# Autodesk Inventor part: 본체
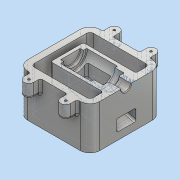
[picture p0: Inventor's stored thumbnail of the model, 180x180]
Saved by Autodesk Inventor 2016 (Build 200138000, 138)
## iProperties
Created: 2018-01
Part Number: 본체
Material: 알루미늄 6061
Document SubType Name: Modeling
Designer: Administrator
Density: 2.7 g/cm^3
Appearance: 알루미늄 - 평지
Mass: 995.304 g
Surface Area: 835.211 cm^2
Volume: 368.631 cm^3
Author: Administrator
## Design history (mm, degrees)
sketch "스케치4"
  geometry: L1 (-55, 55)-(55, 55); L2 (55, 55)-(55, -55); L3 (55, -55)-(-55, -55); L4 (-55, -55)-(-55, 55); L5 (-55, 55)-(55, -55); L6 (55, 55)-(-55, -55); L7 (45, 45)-(-45, 45); L8 (-45, 45)-(-45, -45); L9 (-45, -45)-(45, -45); L10 (45, -45)-(45, 45); 3 further points
  constraints: 20 end point, 2 midpoint, 2 parallel, 2 point on line, 1 horizontal, 1 perpendicular
  dimensions: "d17" = 110 distance of L1.end L2.end; "d18" = 110 distance of L1.start L1.end; "d19" = 90 distance of L9.end L7.start; "d20" = 10 distance between parallel lines of L2 L10; "d21" = 10 distance between parallel lines of L1 L7; "d22" = 10 distance between parallel lines of L4 L8; "d23" = 90 distance of L8.end L9.end
extrude "돌출2" new body sketch "스케치4" distance "d27" = 65; taper "d28" = 0 deg
sketch "스케치5"
  geometry: L1 (-45, -45)-(-45, 45) reference; L2 (-45, 45)-(45, 45) reference; L3 (45, 45)-(45, -45) reference; L4 (45, -45)-(-45, -45) reference; L5 (-55, 55)-(-55, -55) reference; L6 (-55, -55)-(55, -55) reference; L7 (55, -55)-(55, 55) reference; L8 (55, 55)-(-55, 55) reference; L9 (-55, 55)-(55, 55) reference; 1 further point
node "작업 평면1"
sketch "스케치6"
  geometry: L1 (-55, 55)-(55, 55) reference; L2 (-35.5, 65)-(-20.5, 65); L3 (-20.5, 65)-(-20.5, 55); L4 (-20.5, 55)-(-35.5, 55); L5 (-35.5, 55)-(-35.5, 65); L6 (-55, 55)-(-55, -55) reference; A1 r 7.5 centre (-28, 65) between (-20.5, 65) and (-35.5, 65); 1 further point
  constraints: 8 end point, 2 parallel, 2 point on circle, 1 centre point, 1 horizontal, 1 perpendicular, 1 point on line, 1 tangent
  dimensions: "d30" = 7.5 radius of A1; "d31" = 27 distance from line of L6 A1.centre; "d32" = 10 distance from line of A1.centre L1
extrude "돌출3" join sketch "스케치6" distance "d33" = 20; taper "d34" = 0 deg
sketch "스케치8"
  geometry: L1 (110, -65)-(110, 0) reference; L2 (0, 0)-(110, 0) reference; 2 further points
  constraints: 1 other
  dimensions: "d38" = 20 distance from line of L2 point (55, -20); "d39" = 55 distance from line of L1 point (55, -20)
feature "엠보싱1" sketch "스케치8" dims "d17" = 110, "d18" = 110, "d19" = 90, "d20" = 10, "d21" = 10, "d22" = 10, "d23" = 90, "d40" = 0.5, "d41" = 0
hole "구멍1" diameter "d44" = 3.242; stored, may be unused: countersink angle "d48" = 90 deg, drill point angle "d50" = 118 deg; dims "d42" = 10, "d43" = 10, "d45" = 9, "d46" = 4, "d47" = 2, "d49" = 11
sketch "스케치10"
  geometry: L1 (-45, -65)-(-45, -56.436); L2 (-45, -56.436)-(35, -35); L3 (35, -35)-(35, 0); L4 (-45, 0)-(45, 0) reference; L5 (45, -65)-(-45, -65) reference; L6 (55, 0)-(55, -65) reference; L7 (35, 0)-(-45, 0); L8 (-35.5, 0)-(-55, 0) reference; L9 (-45, 0)-(-45, -65) reference; L10 (-45, -65)-(-45, -65); L11 (-45, 0)-(-45, -65) reference; L12 (-45, 0)-(-45, -56.436); 2 further points
  constraints: 12 end point, 3 collinear, 3 point on line, 1 midpoint, 1 parallel, 1 vertical
  dimensions: "d51" = 105 deg angle of L1 L2; "d52" = 30 distance from line of L5 L2.end; "d53" = 20 distance between parallel lines of L6 L3
extrude "돌출4" join sketch "스케치10" stored distance "d54" = 50; taper "d55" = 0 deg
sketch "스케치12"
  geometry: L1 (-45, 0)-(-45, -65) reference; L2 (-45, -56.436)-(35, -35) reference; L3 (35, -35)-(35, 0) reference; L4 (-58.442, 0)-(50.741, 0); L5 (-55, -7.5)-(-36, -7.5); L6 (-36, -7.5)-(-36, -16); L7 (-36, -16)-(-22, -16); L8 (-22, -16)-(-22, -20); L9 (-22, -20)-(25, -20); L10 (25, -20)-(25, -15); L11 (25, -15)-(30, -15); L12 (30, -15)-(30, 0); L13 (35, 0)-(-45, 0) reference; L14 (-55, 0)-(-55, -65) reference; L15 (-55, -7.5)-(-55, 0); L16 (30, 0)-(-55, 0); 2 further points
  constraints: 22 end point, 5 perpendicular, 3 point on line, 2 collinear, 2 horizontal, 2 vertical, 1 midpoint
  dimensions: "d56" = 15 diameter of L5 L4; "d57" = 32 diameter of L7 L4; "d59" = 40 diameter of L9 L4; "d60" = 30 diameter of L11 L4; "d61" = 19 distance of L5.start L5.end; "d62" = 14 distance of L6.end L7.end; "d63" = 47 distance of L8.end L9.end; "d64" = 5 distance of L10.end L11.end
revolve "회전1" sketch "스케치12" stored, may be unused: angle "d65" = 90 deg
sketch "스케치13"
  geometry: L1 (25, -20)-(-22, -20) reference; L2 (-17, -20)-(-17, -25.757); L3 (-17, -25.757)-(-55, -35.939); L4 (20, -20)-(20, -33.843); L5 (20, -33.843)-(-55, -53.939); L6 (35, -35)-(-45, -56.436) reference; L7 (-55, 0)-(-55, -65) reference; L8 (25, 0)-(25, -20) reference; L9 (-22, 0)-(-22, -20) reference; L10 (-17, -20)-(20, -20); L11 (20.5, -20)-(20.5, 0) reference; 1 further point
  constraints: 10 end point, 4 point on line, 2 parallel, 2 vertical, 1 perpendicular
  dimensions: "d66" = 5 distance between parallel lines of L6 L5; "d67" = 37 distance between parallel lines of L4 L2; "d68" = 18 distance of L5.end L3.end; "d71" = 5 distance between parallel lines of L9 L2
extrude "돌출5" cut sketch "스케치13" stored distance "d72" = 30; taper "d73" = 0 deg
sketch "스케치15"
  geometry: L1 (-20, 15)-(17, 15); L2 (17, 15)-(17, -15); L3 (17, -15)-(-20, -15); L4 (-20, -15)-(-20, 15); L5 (36, -7.5)-(36, 7.5) reference; L6 (22, -16)-(22, 16) reference; L7 (-25, -15)-(-25, 15) reference; 3 further points
  constraints: 8 end point, 2 midpoint, 2 parallel, 1 horizontal, 1 horizontal alignment, 1 perpendicular
  dimensions: "d98" = 37 distance of L1.start L1.end; "d100" = 30 distance of L1.end L2.end; "d101" = 5 distance between parallel lines of L6 L2
extrude "돌출6" cut sketch "스케치15" distance "d76" = 21; taper "d77" = 0 deg
fillet "모깎기1" dims "d78" = 15
fillet "모깎기2" dims "d79" = 5
fillet "모깎기3" dims "d80" = 3
fillet "모깎기4" dims "d81" = 3
fillet "모깎기5" dims "d82" = 3
fillet "모깎기6" dims "d83" = 3
fillet "모깎기7" dims "d84" = 3
chamfer "모따기1" distance "d85" = 1; stored, may be unused: second distance "d86" = 2, angle "d87" = 45 deg
chamfer "모따기2" distance "d88" = 1; stored, may be unused: second distance "d89" = 2, angle "d90" = 45 deg
fillet "모깎기8" dims "d94" = 3
fillet "모깎기9" dims "d102" = 3
fillet "모깎기10" dims "d103" = 1
fillet "모깎기11" dims "d104" = 3
node "솔리드2"
pattern_linear "직사각형 패턴1" dims "d37" = 56
mirror "대칭1"
mirror "대칭2"
mirror "대칭3"
